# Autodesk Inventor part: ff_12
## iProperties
Created: 2017-01
Part Number: ff_12
Checked By: TraceParts S.A.
Catalog Web Link: www.traceparts.com
Document SubType Name: Modeling
Designer: TraceParts
Company: TraceParts S.A.
Author: TraceParts
REFERENCE: FF 12
SUPPLIER: Technische Antriebselemente GmbH - Germany
DESIGN: Свободная опора FF
TraceParts.PartNumber: 80-08072009-855310
TRACEPARTS: TRACEPARTS
TraceParts.PartTitle: Свободная опора FF
TraceParts.InstanceId: 80-08072009-855310COUBF80CIFYSGY6GVDA0PIQ31
TraceParts.PartLanguage: ru
TraceParts.ClassPath: TEA_GER:/TEA_GER.1/TEA.120/TEA.120.020/80-08072009-855310
TraceParts.PartVersion: 1.0.7
TraceParts.PartStatus: Published
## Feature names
1. ff_12
